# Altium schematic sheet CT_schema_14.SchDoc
size 386 x 278 mm
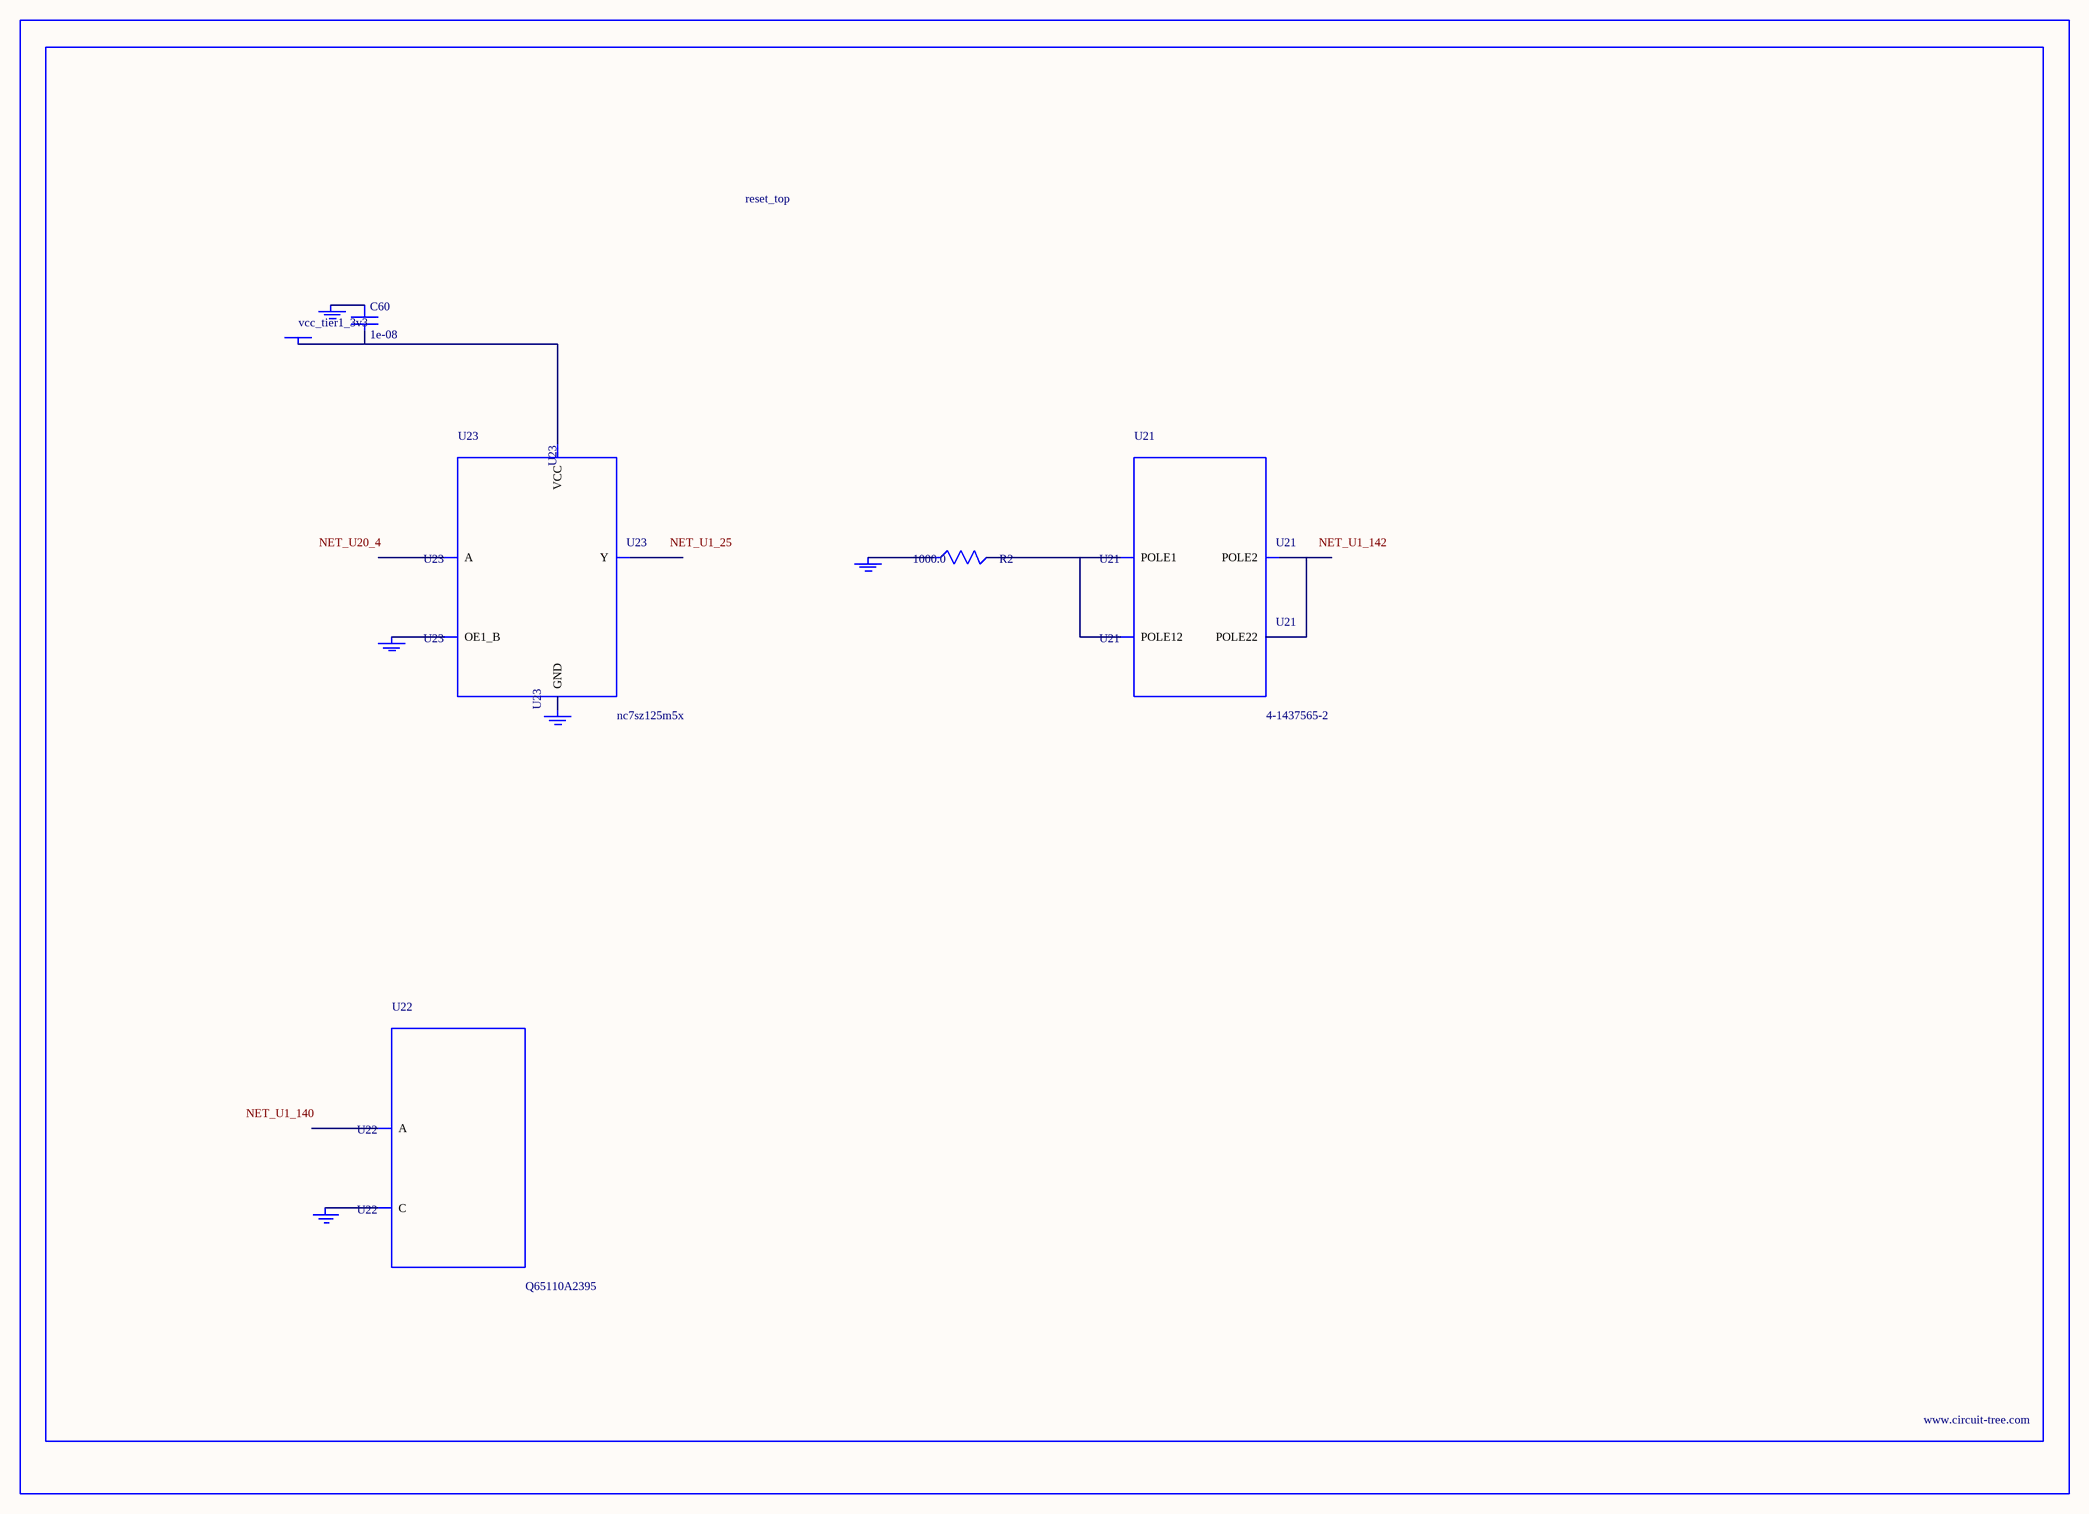
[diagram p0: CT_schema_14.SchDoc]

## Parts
BORDER13  (no value)
C60  1e-08  [C0402]
GND_INSTANCE_13_0  (no value)
GND_INSTANCE_13_1  (no value)
GND_INSTANCE_13_2  (no value)
GND_INSTANCE_13_3  (no value)
GND_INSTANCE_13_4  (no value)
POWER_INSTANCE_13_0  vcc_tier1_3v3
R2  1000.0  [R0603]
U21  4-1437565-2  [SW_4-1437565-2]
U22  Q65110A2395  [LGM67K-G1J2-24-Z]
U23  nc7sz125m5x  [NC7SZ125M5X]

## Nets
NetC60_1: C60.1 GND_INSTANCE_13_2.0(GND)
NetC60_2: C60.2 POWER_INSTANCE_13_0.0(PWR) U23.5(VCC)
NetGND_INSTANCE_13_0_0: GND_INSTANCE_13_0.0(GND) R2.1
NetGND_INSTANCE_13_1_0: GND_INSTANCE_13_1.0(GND) U22.C
NetGND_INSTANCE_13_3_0: GND_INSTANCE_13_3.0(GND) U23.1(OE1_B)
NetGND_INSTANCE_13_4_0: GND_INSTANCE_13_4.0(GND) U23.3(GND)
NetR2_2: R2.2 U21.1(POLE1) U21.2(POLE12)
NetU21_3: U21.3(POLE2) U21.4(POLE22)

Not connected (* = marked no-connect by the designer): U22 A; U23 2(A) 4(Y)

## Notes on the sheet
- Labels drawn without touching a wire or pin: NET_U1_25, NET_U1_140, NET_U1_142, NET_U20_4

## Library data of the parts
BORDER13 = BORDER_PAGE13
C60 = C0402C103K3RAC
GND_INSTANCE_13_0-GND_INSTANCE_13_4 = GND
POWER_INSTANCE_13_0 = PWR
R2 = RC0603JR-071KL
